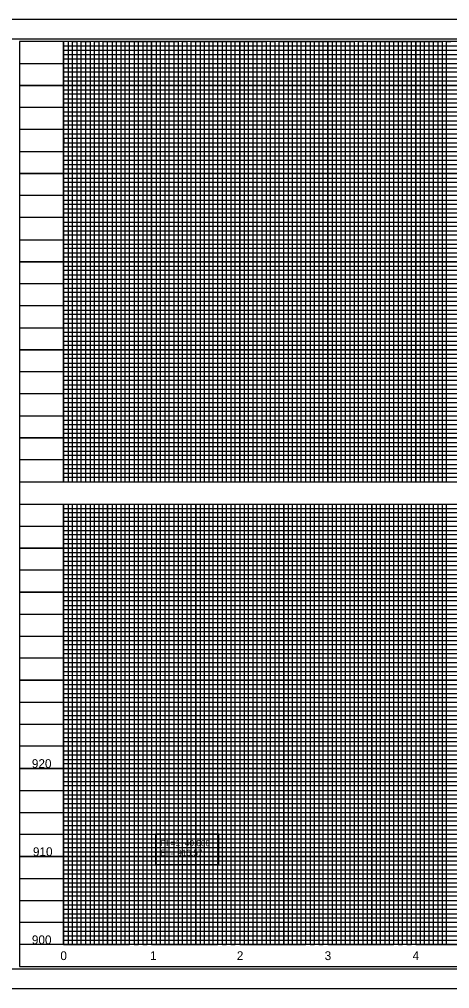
# Model space of a CAD drawing. Extents: x 1648123 to 1650776, y 802691 to 803791.
# Drawn here: x 1649029 to 1649518, y 802691 to 803791 of the extents above; entities that cross this region are included whole.
import ezdxf

# ---------------------------------------------------------------- set-up
doc = ezdxf.new("R2010")
doc.units = 0
for name, color, linetype in [('Exist Vertical Profile Horizontal Axis Label Major', 7, 'Continuous'), ('Exist Vertical Profile Vertical Axis Label', 7, 'Continuous'), ('Prop Grid Mask', 7, 'Continuous'), ('Prop VPI Ditch Grade Right Label', 7, 'Continuous'), ('Sheet Cutting Line CELL', 7, 'Continuous'), ('Sheet DOT Grid CELL', 7, 'Continuous'), ('Sheet Layout Profile Border Port 1', 7, 'Continuous'), ('Sheet Layout Profile Border Port 2', 7, 'Continuous'), ('Sheet Plot Border Inside CELL', 7, 'Continuous'), ('Sheet Plot Border Outside CELL', 7, 'Continuous'), ('Sheet Profile CELL', 7, 'Continuous'), ('Sheet Profile Grid Major CELL', 7, 'Continuous'), ('Sheet Profile Grid Middle CELL', 7, 'Continuous'), ('Sheet Profile Grid Minor CELL', 7, 'Continuous')]:
    doc.layers.add(name, color=color, linetype=linetype)

msp = doc.modelspace()

# ---------------------------------------------------------------- linework, layer by layer
at = {"layer": 'Prop Grid Mask'}
msp.add_lwpolyline([(1649183.7, 802866.3), (1649183.7, 802831.9), (1649255.7, 802831.9), (1649255.7, 802866.3)], close=True, dxfattribs=at)
at = {"layer": 'Sheet Cutting Line CELL'}
for p, q in [((1650546.3, 803791), (1648862.3, 803791)), ((1648862.3, 802691), (1650546.3, 802691))]:
    msp.add_line(p, q, dxfattribs=at)
at = {"layer": 'Sheet DOT Grid CELL'}
for p, q in [((1649079.3, 803266), (1649079.3, 803766)), ((1649129.3, 803266), (1649129.3, 803766)), ((1649179.3, 803266), (1649179.3, 803766)), ((1649229.3, 803266), (1649229.3, 803766)), ((1649279.3, 803266), (1649279.3, 803766)), ((1649329.3, 803266), (1649329.3, 803766)), ((1649379.3, 803266), (1649379.3, 803766)), ((1649429.3, 803266), (1649429.3, 803766)), ((1649479.3, 803266), (1649479.3, 803766)), ((1650329.2, 803716), (1649029.3, 803716)), ((1650329.2, 803666), (1649029.3, 803666)), ((1650329.3, 803616), (1649029.3, 803616)), ((1650529.3, 803566), (1649029.3, 803566)), ((1650529.3, 803516), (1649029.3, 803516)), ((1650529.3, 803466), (1649029.3, 803466)), ((1650529.3, 803416), (1649029.3, 803416)), ((1650529.3, 803366), (1649029.3, 803366)), ((1650529.3, 803316), (1649029.3, 803316)), ((1649029.3, 803241), (1650529.2, 803241)), ((1649079.3, 803241), (1649079.3, 802741)), ((1649129.3, 803241), (1649129.3, 802741)), ((1649179.3, 803241), (1649179.3, 802741)), ((1649229.3, 803241), (1649229.3, 802741)), ((1649279.3, 803241), (1649279.3, 802741)), ((1649329.3, 803241), (1649329.3, 802741)), ((1649379.3, 803241), (1649379.3, 802741)), ((1649429.3, 803241), (1649429.3, 802741)), ((1649479.3, 803241), (1649479.3, 802741)), ((1649029.3, 803191), (1650529.2, 803191)), ((1649029.3, 803141), (1650529.2, 803141)), ((1649029.3, 803091), (1650529.2, 803091)), ((1649029.3, 803041), (1650529.2, 803041)), ((1649029.3, 802991), (1650529.2, 802991)), ((1649029.3, 802941), (1650529.2, 802941)), ((1649029.3, 802891), (1650529.2, 802891)), ((1649029.3, 802841), (1650529.2, 802841)), ((1649029.3, 802791), (1650529.2, 802791))]:
    msp.add_line(p, q, dxfattribs=at)
at = {"layer": 'Sheet Layout Profile Border Port 1'}
msp.add_lwpolyline([(1649079.3, 803605), (1649079.3, 803266), (1650479.3, 803266), (1650479.3, 803605)], dxfattribs=at)
at = {"layer": 'Sheet Layout Profile Border Port 2'}
msp.add_lwpolyline([(1649079.3, 803241), (1650479.3, 803241), (1650479.3, 802741), (1649079.3, 802741)], close=True, dxfattribs=at)
at = {"layer": 'Sheet Plot Border Inside CELL'}
msp.add_lwpolyline([(1648875.3, 802713.5), (1650541.8, 802713.5), (1650541.8, 803768.6), (1648875.3, 803768.6)], close=True, dxfattribs=at)
at = {"layer": 'Sheet Plot Border Outside CELL'}
msp.add_lwpolyline([(1648862.3, 802691), (1650546.3, 802691), (1650546.3, 803791), (1648862.3, 803791)], close=True, dxfattribs=at)
at = {"layer": 'Sheet Profile CELL'}
for p, q in [((1649029.3, 803266), (1650529.3, 803266)), ((1649029.3, 803241), (1650529.3, 803241)), ((1650529.3, 802741), (1649029.3, 802741)), ((1649029.3, 802716), (1650529.3, 802716)), ((1649029.3, 802716), (1649029.3, 802716)), ((1649029.3, 802716), (1649029.3, 802716)), ((1649029.3, 802716), (1649029.3, 802716)), ((1649029.3, 802716), (1649029.3, 802716)), ((1649029.3, 802716), (1649029.3, 802716)), ((1649029.3, 802716), (1649029.3, 802716)), ((1649029.3, 802716), (1649029.3, 802716))]:
    msp.add_line(p, q, dxfattribs=at)
msp.add_lwpolyline([(1650529.3, 803766), (1649029.3, 803766), (1649029.3, 802716), (1650529.3, 802716)], close=True, dxfattribs=at)
msp.add_lwpolyline([(1649066.8, 802716), (1649066.8, 802716)], dxfattribs=at)
at = {"layer": 'Sheet Profile Grid Major CELL'}
msp.add_line((1649029.3, 802741), (1649029.3, 802741), dxfattribs=at)
for points in [[(1649079.3, 803766), (1649079.3, 803266), (1649129.3, 803266), (1649129.3, 803766), (1649179.3, 803766), (1649179.3, 803266), (1649229.3, 803266), (1649229.3, 803766), (1649279.3, 803766), (1649279.3, 803266), (1649329.3, 803266), (1649329.3, 803766), (1649379.3, 803766), (1649379.3, 803266), (1649429.3, 803266), (1649429.3, 803766), (1649479.3, 803766), (1649479.3, 803266), (1649529.3, 803266)], [(1649029.3, 803716), (1650329.3, 803716)], [(1650329.3, 803666), (1649029.3, 803666), (1649029.3, 803616), (1650329.3, 803616)], [(1650529.3, 803566), (1649029.3, 803566), (1649029.3, 803516), (1650529.3, 803516)], [(1650529.3, 803466), (1649029.3, 803466), (1649029.3, 803416), (1650529.3, 803416)], [(1650529.3, 803366), (1649029.3, 803366), (1649029.3, 803366), (1649029.3, 803316), (1650529.3, 803316)], [(1649079.3, 803241), (1649079.3, 802741), (1649129.3, 802741), (1649129.3, 803241), (1649179.3, 803241), (1649179.3, 802741), (1649229.3, 802741), (1649229.3, 803241), (1649279.3, 803241), (1649279.3, 802741), (1649329.3, 802741), (1649329.3, 803241), (1649379.3, 803241), (1649379.3, 802741), (1649429.3, 802741), (1649429.3, 803241), (1649479.3, 803241), (1649479.3, 802741), (1649529.3, 802741)], [(1650529.3, 803191), (1649029.3, 803191)], [(1650529.3, 803141), (1649029.3, 803141), (1649029.3, 803091), (1650529.3, 803091)], [(1650529.3, 803041), (1649029.3, 803041), (1649029.3, 802991), (1650529.3, 802991)], [(1650529.3, 802941), (1649029.3, 802941), (1649029.3, 802891), (1650529.3, 802891)], [(1650529.3, 802841), (1649029.3, 802841), (1649029.3, 802841), (1649029.3, 802791), (1650529.3, 802791)], [(1650529.3, 802741), (1649029.3, 802741)]]:
    msp.add_lwpolyline(points, dxfattribs=at)
at = {"layer": 'Sheet Profile Grid Middle CELL'}
msp.add_line((1649029.3, 803741), (1650179.3, 803741), dxfattribs=at)
for points in [[(1649104.3, 803766), (1649104.3, 803266), (1649154.3, 803266), (1649154.3, 803766), (1649204.3, 803766), (1649204.3, 803266), (1649254.3, 803266), (1649254.3, 803766), (1649304.3, 803766), (1649304.3, 803266), (1649354.3, 803266), (1649354.3, 803766), (1649404.3, 803766), (1649404.3, 803266), (1649454.3, 803266), (1649454.3, 803766), (1649504.3, 803766), (1649504.3, 803266), (1649554.3, 803266)], [(1650329.3, 803691), (1649029.3, 803691), (1649029.3, 803641), (1650329.3, 803641)], [(1650529.3, 803591), (1649029.3, 803591), (1649029.3, 803541), (1650354.3, 803541)], [(1650529.3, 803491), (1649029.3, 803491), (1649029.3, 803441), (1650529.3, 803441)], [(1650529.3, 803391), (1649029.3, 803391), (1649029.3, 803341), (1650529.3, 803341)], [(1650529.3, 803291), (1649029.3, 803291)], [(1649054.3, 803241), (1649104.3, 803241), (1649104.3, 802741), (1649154.3, 802741), (1649154.3, 803241), (1649204.3, 803241), (1649204.3, 802741), (1649254.3, 802741), (1649254.3, 803241), (1649304.3, 803241), (1649304.3, 802741), (1649354.3, 802741), (1649354.3, 803241), (1649404.3, 803241), (1649404.3, 802741), (1649454.3, 802741), (1649454.3, 803241), (1649504.3, 803241), (1649504.3, 802741), (1649554.3, 802741)], [(1649029.3, 803216), (1650529.3, 803216)], [(1650529.3, 803166), (1649029.3, 803166), (1649029.3, 803116), (1650529.3, 803116)], [(1650529.3, 803066), (1649029.3, 803066), (1649029.3, 803016), (1650529.3, 803016)], [(1650529.3, 802966), (1649029.3, 802966), (1649029.3, 802916), (1650529.3, 802916)], [(1650529.3, 802866), (1649029.3, 802866), (1649029.3, 802816), (1650529.3, 802816)], [(1650529.3, 802766), (1649029.3, 802766)]]:
    msp.add_lwpolyline(points, dxfattribs=at)
at = {"layer": 'Sheet Profile Grid Minor CELL'}
for p, q in [((1649079.3, 803761), (1650179.3, 803761)), ((1649079.3, 803756), (1649079.3, 803756)), ((1649079.3, 803756), (1649079.3, 803756)), ((1649079.3, 803756), (1649079.3, 803756)), ((1650179.3, 803756), (1649079.3, 803755.7)), ((1649079.3, 803751), (1650179.3, 803751)), ((1650329.2, 803631), (1649079.3, 803631)), ((1650329.3, 803626), (1649079.3, 803626)), ((1650329.3, 803621), (1649079.3, 803621)), ((1649079.3, 803611), (1650329.3, 803611)), ((1650329.3, 803606), (1649079.3, 803606)), ((1649079.3, 803601), (1650479.3, 803601)), ((1650479.3, 803581), (1649079.3, 803581)), ((1649079.3, 803576), (1650479.3, 803576)), ((1650479.3, 803556), (1649079.3, 803556)), ((1649079.3, 803551), (1650479.3, 803551)), ((1650479.3, 803531), (1649079.3, 803531)), ((1649079.3, 803526), (1650479.3, 803526)), ((1650479.3, 803521), (1649079.3, 803521)), ((1649079.3, 803511), (1650479.3, 803511)), ((1650479.3, 803506), (1649079.3, 803506)), ((1649079.3, 803501), (1650479.3, 803501)), ((1650479.3, 803496), (1649079.3, 803496)), ((1649079.3, 803486), (1650479.3, 803486)), ((1650479.3, 803481), (1649079.3, 803481)), ((1649079.3, 803476), (1650479.3, 803476)), ((1650479.3, 803471), (1649079.3, 803471)), ((1649079.3, 803461), (1650479.3, 803461)), ((1650479.3, 803456), (1649079.3, 803456)), ((1649079.3, 803451), (1650479.3, 803451)), ((1650479.3, 803446), (1649079.3, 803446)), ((1649079.3, 803436), (1650479.3, 803436)), ((1650479.3, 803431), (1649079.3, 803431)), ((1649079.3, 803426), (1650479.3, 803426)), ((1650479.3, 803421), (1649079.3, 803421)), ((1649079.3, 803411), (1650479.3, 803411)), ((1650479.3, 803406), (1649079.3, 803406)), ((1649079.3, 803401), (1650479.3, 803401)), ((1650479.3, 803396), (1649079.3, 803396)), ((1649079.3, 803386), (1650479.3, 803386)), ((1650479.3, 803381), (1649079.3, 803381)), ((1650479.3, 803376), (1649079.3, 803376)), ((1650479.3, 803371), (1649079.3, 803371)), ((1649079.3, 803361), (1650479.3, 803361)), ((1650479.3, 803356), (1649079.3, 803356)), ((1649079.3, 803351), (1650479.3, 803351)), ((1650479.3, 803346), (1649079.3, 803346)), ((1649079.3, 803336), (1650479.3, 803336)), ((1650479.3, 803331), (1649079.3, 803331)), ((1649079.3, 803326), (1650479.3, 803326)), ((1650479.3, 803321), (1649079.3, 803321)), ((1649079.3, 803311), (1650479.3, 803311)), ((1650479.3, 803306), (1649079.3, 803306)), ((1649079.3, 803301), (1650479.3, 803301)), ((1650479.3, 803296), (1649079.3, 803296)), ((1649079.3, 803286), (1650479.3, 803286)), ((1650479.3, 803281), (1649079.3, 803281)), ((1649079.3, 803276), (1650479.3, 803276)), ((1649079.3, 803236), (1650479.3, 803236)), ((1650479.3, 803231), (1649079.3, 803231)), ((1649079.3, 803226), (1650479.3, 803226)), ((1650479.3, 803221), (1649079.3, 803221)), ((1649079.3, 803211), (1650479.3, 803211)), ((1650479.3, 803206), (1649079.3, 803206)), ((1649079.3, 803201), (1650479.3, 803201)), ((1650479.3, 803196), (1649079.3, 803196)), ((1649079.3, 803186), (1650479.3, 803186)), ((1650479.3, 803181), (1649079.3, 803181)), ((1649079.3, 803176), (1650479.3, 803176)), ((1650479.3, 803171), (1649079.3, 803171)), ((1649079.3, 803161), (1650479.3, 803161)), ((1650479.3, 803156), (1649079.3, 803156)), ((1649079.3, 803151), (1650479.3, 803151)), ((1650479.3, 803146), (1649079.3, 803146)), ((1649079.3, 803136), (1650479.3, 803136)), ((1650479.3, 803131), (1649079.3, 803131)), ((1649079.3, 803126), (1650479.3, 803126)), ((1650479.3, 803121), (1649079.3, 803121)), ((1649079.3, 803111), (1650479.3, 803111)), ((1650479.3, 803106), (1649079.3, 803106)), ((1649079.3, 803101), (1650479.3, 803101)), ((1650479.3, 803096), (1649079.3, 803096)), ((1649079.3, 803086), (1650479.3, 803086)), ((1650479.3, 803081), (1649079.3, 803081)), ((1649079.3, 803076), (1650479.3, 803076)), ((1650479.3, 803071), (1649079.3, 803071)), ((1649079.3, 803061), (1650479.3, 803061)), ((1650479.3, 803056), (1649079.3, 803056)), ((1649079.3, 803051), (1650479.3, 803051)), ((1650479.3, 803046), (1649079.3, 803046.2)), ((1649079.3, 803036), (1650479.3, 803036)), ((1650479.3, 803031), (1649079.3, 803031)), ((1649079.3, 803026), (1650479.3, 803026)), ((1650479.3, 803021), (1649079.3, 803021)), ((1649079.3, 803011), (1650479.3, 803011)), ((1650479.3, 803006), (1649079.3, 803006)), ((1649079.3, 803001), (1650479.3, 803001)), ((1650479.3, 802996), (1649079.3, 802996)), ((1649079.3, 802986), (1650479.3, 802986)), ((1650479.3, 802981), (1649079.3, 802981)), ((1649079.3, 802976), (1650479.3, 802976)), ((1650479.3, 802971), (1649079.3, 802971)), ((1649079.3, 802961), (1650479.3, 802961)), ((1650479.3, 802956), (1649079.3, 802956)), ((1649079.3, 802951), (1650479.3, 802951)), ((1650479.3, 802946), (1649079.3, 802946)), ((1649079.3, 802936), (1650479.3, 802936)), ((1650479.3, 802931), (1649079.3, 802931)), ((1649079.3, 802926), (1650479.3, 802926)), ((1650479.3, 802921), (1649079.3, 802921)), ((1649079.3, 802911), (1650479.3, 802911)), ((1650479.3, 802906), (1649079.3, 802906)), ((1649079.3, 802901), (1650479.3, 802901)), ((1650479.3, 802896), (1649079.3, 802896)), ((1649079.3, 802886), (1650479.3, 802886)), ((1650479.3, 802881), (1649079.3, 802881)), ((1649079.3, 802876), (1650479.3, 802876)), ((1650479.3, 802871), (1649079.3, 802871)), ((1649079.3, 802861), (1650479.3, 802861)), ((1650479.3, 802856), (1649079.3, 802856)), ((1649079.3, 802851), (1650479.3, 802851)), ((1650479.3, 802846), (1649079.3, 802846)), ((1649079.3, 802836), (1650479.3, 802836)), ((1650479.3, 802831), (1649079.3, 802831)), ((1649079.3, 802826), (1650479.3, 802826)), ((1650479.3, 802821), (1649079.3, 802821)), ((1649079.3, 802811), (1650479.3, 802811)), ((1650479.3, 802806), (1649079.3, 802806)), ((1649079.3, 802801), (1650479.3, 802801)), ((1650479.3, 802796), (1649079.3, 802796)), ((1649079.3, 802786), (1650479.3, 802786)), ((1650479.3, 802781), (1649079.3, 802781)), ((1649079.3, 802776), (1650479.3, 802776)), ((1650479.3, 802771), (1649079.3, 802771)), ((1649079.3, 802761), (1650479.3, 802761)), ((1650479.3, 802756), (1649079.3, 802756)), ((1649079.3, 802751), (1650479.3, 802751)), ((1649079.3, 802746), (1650479.3, 802746))]:
    msp.add_line(p, q, dxfattribs=at)
for points in [[(1649084.3, 803766), (1649084.3, 803266), (1649089.3, 803266), (1649089.3, 803766), (1649094.3, 803766), (1649094.3, 803266), (1649099.3, 803266), (1649099.3, 803766), (1649109.3, 803766), (1649109.3, 803266), (1649114.3, 803266), (1649114.3, 803766), (1649119.3, 803766), (1649119.3, 803266), (1649124.3, 803266), (1649134.3, 803266), (1649139.3, 803266), (1649139.3, 803766), (1649144.3, 803766), (1649144.3, 803266), (1649149.3, 803266), (1649149.3, 803766), (1649159.3, 803766), (1649159.3, 803266), (1649164.3, 803266), (1649164.3, 803766), (1649169.3, 803766), (1649169.3, 803266), (1649174.3, 803266), (1649174.3, 803766), (1649184.3, 803766), (1649184.3, 803266), (1649189.3, 803266), (1649189.3, 803766), (1649194.3, 803766), (1649194.3, 803266), (1649199.3, 803266), (1649199.3, 803766), (1649209.3, 803766), (1649209.3, 803266), (1649214.3, 803266), (1649214.3, 803766), (1649219.3, 803766), (1649219.3, 803266), (1649224.3, 803266), (1649224.3, 803766), (1649234.3, 803766), (1649234.3, 803266), (1649239.3, 803266), (1649239.3, 803766), (1649244.3, 803766), (1649244.3, 803266), (1649249.3, 803266), (1649249.3, 803766), (1649259.3, 803766), (1649259.3, 803266), (1649264.3, 803266), (1649264.3, 803766), (1649269.3, 803766), (1649269.3, 803266), (1649274.3, 803266), (1649274.3, 803766), (1649284.3, 803766), (1649284.3, 803266), (1649289.3, 803266), (1649289.3, 803766), (1649294.3, 803766), (1649294.3, 803266)], [(1649124.3, 803266), (1649124.3, 803766), (1649134.3, 803766), (1649134.3, 803266)], [(1649294.3, 803266), (1649299.3, 803266), (1649299.3, 803766), (1649309.3, 803766), (1649309.3, 803266), (1649314.3, 803266), (1649314.3, 803766), (1649319.3, 803766), (1649319.3, 803266), (1649324.3, 803266), (1649324.3, 803766), (1649334.3, 803766), (1649334.3, 803266), (1649339.3, 803266), (1649339.3, 803766), (1649344.3, 803766), (1649344.3, 803266), (1649349.3, 803266), (1649349.3, 803766), (1649359.3, 803766), (1649359.3, 803266), (1649364.3, 803266), (1649364.3, 803766), (1649369.3, 803766), (1649369.3, 803266), (1649374.3, 803266), (1649374.3, 803766), (1649384.3, 803766), (1649384.3, 803266), (1649389.3, 803266), (1649389.3, 803766), (1649394.3, 803766), (1649394.3, 803266), (1649399.3, 803266), (1649399.3, 803766), (1649409.3, 803766), (1649409.3, 803266), (1649414.3, 803266), (1649414.3, 803766), (1649419.3, 803766), (1649419.3, 803266), (1649424.3, 803266), (1649424.3, 803766), (1649434.3, 803766), (1649434.3, 803266), (1649439.3, 803266), (1649439.3, 803766), (1649444.3, 803766), (1649444.3, 803266), (1649449.3, 803266), (1649449.3, 803766), (1649459.3, 803766), (1649459.3, 803266), (1649464.3, 803266), (1649464.3, 803766), (1649469.3, 803766), (1649469.3, 803266), (1649474.3, 803266), (1649474.3, 803766), (1649484.3, 803766), (1649484.3, 803266), (1649489.3, 803266), (1649489.3, 803766), (1649494.3, 803766), (1649494.3, 803266), (1649499.3, 803266), (1649499.3, 803766), (1649509.3, 803766), (1649509.3, 803266), (1649514.3, 803266), (1649514.3, 803766), (1649519.3, 803766)], [(1650179.3, 803746), (1649079.3, 803746), (1649079.3, 803736), (1650329.3, 803736)], [(1650329.2, 803731), (1649079.3, 803731), (1649079.3, 803726), (1650329.3, 803726)], [(1650329.3, 803721), (1649079.3, 803721), (1649079.3, 803711), (1650329.3, 803711)], [(1650329.3, 803706), (1649079.3, 803706), (1649079.3, 803701), (1650329.3, 803701)], [(1650329.3, 803696), (1649079.3, 803696), (1649079.3, 803686), (1650329.3, 803686)], [(1650329.3, 803681), (1649079.3, 803681), (1649079.3, 803676), (1650329.3, 803676)], [(1650329.3, 803671), (1649079.3, 803671), (1649079.3, 803661), (1650329.3, 803661)], [(1650329.3, 803655.9), (1649079.4, 803655.9), (1649079.4, 803651), (1650329.3, 803651)], [(1650329.3, 803646), (1649079.3, 803646), (1649079.3, 803636), (1650329.3, 803636)], [(1650479.3, 803596), (1649079.3, 803596), (1649079.3, 803586), (1650479.3, 803586)], [(1650479.3, 803571), (1649079.3, 803571), (1649079.3, 803561), (1650479.3, 803561)], [(1650479.3, 803546), (1649079.3, 803546), (1649079.3, 803536), (1650479.3, 803536)], [(1650479.3, 803271), (1649079.3, 803271)], [(1649079.3, 803241), (1649084.3, 803241), (1649084.3, 802741), (1649089.3, 802741), (1649089.3, 803241), (1649094.3, 803241), (1649094.3, 802741), (1649099.3, 802741), (1649099.3, 803241), (1649109.3, 803241), (1649109.3, 802741), (1649114.3, 802741), (1649114.3, 803241), (1649119.3, 803241), (1649119.3, 802741), (1649124.3, 802741), (1649134.3, 802741), (1649139.3, 802741), (1649139.3, 803241), (1649144.3, 803241), (1649144.3, 802741), (1649149.3, 802741), (1649149.3, 803241), (1649159.3, 803241), (1649159.3, 802741), (1649164.3, 802741), (1649164.3, 803241), (1649169.3, 803241), (1649169.3, 802741), (1649174.3, 802741), (1649174.3, 803241), (1649184.3, 803241), (1649184.3, 802741), (1649189.3, 802741), (1649189.3, 803241), (1649194.3, 803241), (1649194.3, 802741), (1649199.3, 802741), (1649199.3, 803241), (1649209.3, 803241), (1649209.3, 802741), (1649214.3, 802741), (1649214.3, 803241), (1649219.3, 803241), (1649219.3, 802741), (1649224.3, 802741), (1649224.3, 803241), (1649234.3, 803241), (1649234.3, 802741), (1649239.3, 802741), (1649239.3, 803241), (1649244.3, 803241), (1649244.3, 802741), (1649249.3, 802741), (1649249.3, 803241), (1649259.3, 803241), (1649259.3, 802741), (1649264.3, 802741), (1649264.3, 803241), (1649269.3, 803241), (1649269.3, 802741), (1649274.3, 802741), (1649274.3, 803241), (1649284.3, 803241), (1649284.3, 802741), (1649289.3, 802741), (1649289.3, 803241), (1649294.3, 803241), (1649294.3, 802741)], [(1649124.3, 802741), (1649124.3, 803241), (1649134.3, 803241), (1649134.3, 802741)], [(1649294.3, 802741), (1649299.3, 802741), (1649299.3, 803241), (1649309.3, 803241), (1649309.3, 802741), (1649314.3, 802741), (1649314.3, 803241), (1649319.3, 803241), (1649319.3, 802741), (1649324.3, 802741), (1649324.3, 803241), (1649334.3, 803241), (1649334.3, 802741), (1649339.3, 802741), (1649339.3, 803241), (1649344.3, 803241), (1649344.3, 802741), (1649349.3, 802741), (1649349.3, 803241), (1649359.3, 803241), (1649359.3, 802741), (1649364.3, 802741), (1649364.3, 803241), (1649369.3, 803241), (1649369.3, 802741), (1649374.3, 802741), (1649374.3, 803241), (1649384.3, 803241), (1649384.3, 802741), (1649389.3, 802741), (1649389.3, 803241), (1649394.3, 803241), (1649394.3, 802741), (1649399.3, 802741), (1649399.3, 803241), (1649409.3, 803241), (1649409.3, 802741), (1649414.3, 802741), (1649414.3, 803241), (1649419.3, 803241), (1649419.3, 802741), (1649424.3, 802741), (1649424.3, 803241), (1649434.3, 803241), (1649434.3, 802741), (1649439.3, 802741), (1649439.3, 803241), (1649444.3, 803241), (1649444.3, 802741), (1649449.3, 802741), (1649449.3, 803241), (1649459.3, 803241), (1649459.3, 802741), (1649464.3, 802741), (1649464.3, 803241), (1649469.3, 803241), (1649469.3, 802741), (1649474.3, 802741), (1649474.3, 803241), (1649484.3, 803241), (1649484.3, 802741), (1649489.3, 802741), (1649489.3, 803241), (1649494.3, 803241), (1649494.3, 802741), (1649499.3, 802741), (1649499.3, 803241), (1649509.3, 803241), (1649509.3, 802741), (1649514.3, 802741), (1649514.3, 803241), (1649519.3, 803241)]]:
    msp.add_lwpolyline(points, dxfattribs=at)

# ---------------------------------------------------------------- texts
at = {"layer": 'Exist Vertical Profile Horizontal Axis Label Major'}
for s, p in [('0', (1649075.6, 802723.4)), ('1', (1649177.5, 802723.4)), ('2', (1649276, 802723.4)), ('3', (1649375.8, 802723.4)), ('4', (1649475.7, 802723.4))]:
    msp.add_text(s, height=10, dxfattribs=at).set_placement(p)
at = {"layer": 'Exist Vertical Profile Vertical Axis Label'}
for s, p in [('920', (1649043.2, 802941.4)), ('910', (1649044.4, 802841.4)), ('900', (1649043.2, 802741.4))]:
    msp.add_text(s, height=10, dxfattribs=at).set_placement(p)
at = {"layer": 'Prop VPI Ditch Grade Right Label'}
for s, p in [('PI =1+40.000', (1649189.4, 802852.7)), ('El = 916.57', (1649189.4, 802841.7))]:
    msp.add_text(s, height=7, dxfattribs=at).set_placement(p)

doc.saveas('drawing.dxf')
